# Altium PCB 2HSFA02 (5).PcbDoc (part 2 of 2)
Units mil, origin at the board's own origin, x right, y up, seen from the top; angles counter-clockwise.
Board outline 4391.67 x 3028.12 mil, 2 copper layers (Top Layer, Bottom Layer); 97 components, 133 nets, 219 pads, 38 vias.
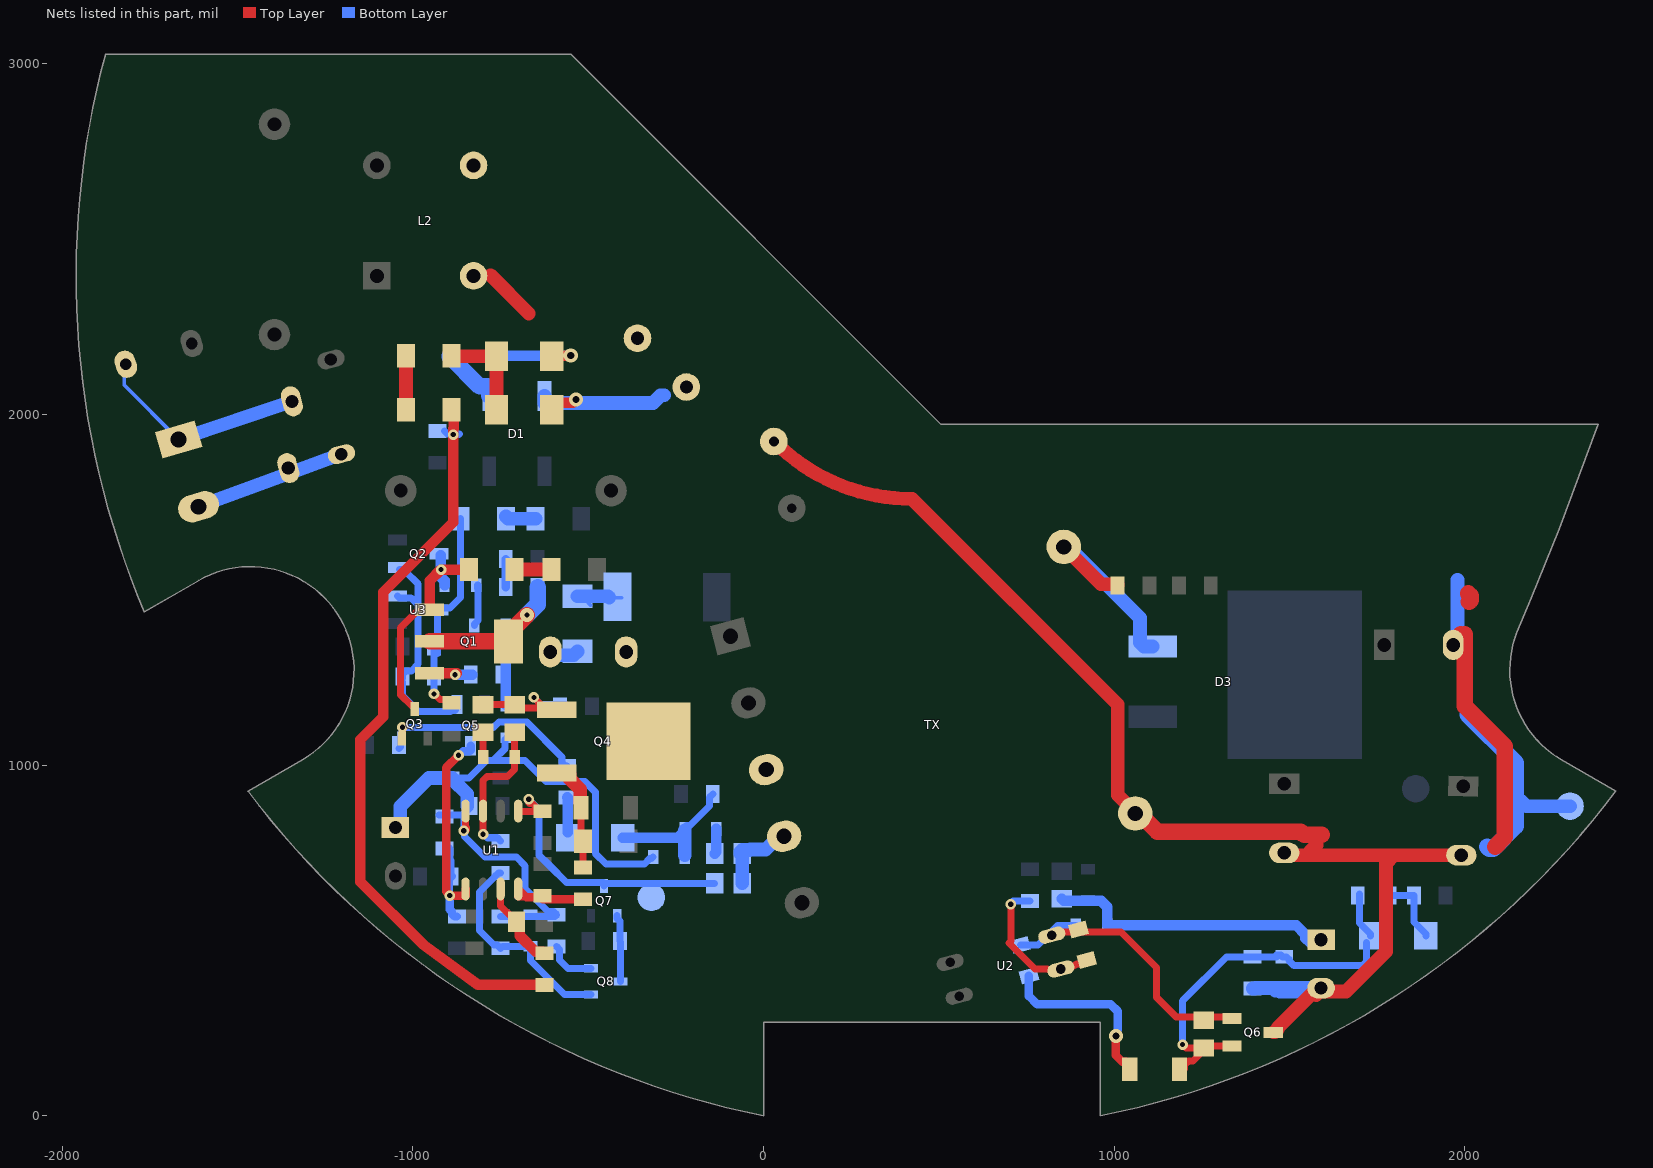
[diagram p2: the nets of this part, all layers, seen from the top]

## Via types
v1: diameter 30, hole 15, Top Layer to Bottom Layer, 22 vias
v2: diameter 40, hole 20, Top Layer to Bottom Layer, 15 vias
v3: diameter 39.37, hole 15, Top Layer to Bottom Layer, 1 vias

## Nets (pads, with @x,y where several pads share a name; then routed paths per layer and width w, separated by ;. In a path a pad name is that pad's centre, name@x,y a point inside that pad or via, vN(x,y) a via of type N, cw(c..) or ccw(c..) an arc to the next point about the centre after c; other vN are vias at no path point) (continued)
NetC8_1: C8.1 C13.2 D10.K D11.K D13.K D18.K R11.2 R30.1 R33.1 U1.8 | length 2063.7
  Top Layer w20: v1(-855,813) -848.83,813 -846.91,814.91 -846.91,821.98 -850.69,825.76 -850.69,868.53 U1.8@-850,869.22
  Top Layer w39.37: C8.1@-1050,821.9 -1040.16,821.9 C8.1@-1030.32,831.74
  Bottom Layer w20: R11.2@-926.16,858 -860.28,858 -849.98,868.29 -840.3,877.98 C13.2@-835.28,883 ; D13.K@-890.87,963 -887.91,963 -840,963 -790,1013 -771.77,1013 ; -854.96,855.73 -855,855.69 v1(-855,813) -853.09,811.09 -853.09,796.09 -795,738 -705,738 -680,713 -680,648 -614.96,582.96 -599.69,582.96 R33.1@-590,573.28 -595,568.28 -665,568.28 R30.1@-750,568.28 ; D10.K@-730,1078 -732.06,1078 -736.82,1073.24 -736.82,1047.95 -771.77,1013 ; D11.K@-315,738.08 -319.76,733.32 -324.69,733.32 -340,718 -450,718 -480,748 -480,923 -510,953 -620,953 -680,1013 -771.77,1013
  Bottom Layer w39.37: C8.1@-1050,821.9 -1046.06,821.9 -1036.21,831.74 -1036.21,881.79 -955,963 -893.82,963 D13.K@-890.87,963 ; D13.K@-887.91,963 -886.93,962.02 -886.93,959.06 -845.28,917.41 C13.2@-845.28,883
NetC9_2: C9.2 D9.K D11.A D12.K | length 406.6
  Bottom Layer w20: D12.K@-225,818 D12.K@-220,818 ; D12.K@-220.24,818 -220.24,827.69 -210.31,827.69 -154.41,883.59 -154.41,908.31 C9.2@-144.72,918
  Bottom Layer w30: D9.K@-401.26,793 -245,793 -225,813 D12.K@-225,818 D12.K@-225,813.55
  Bottom Layer w39.37: D11.A@-225,743 D12.K@-225,813.55
NetC10_2: C10.2 Q5.3 R11.1 R12.2 U1.1 | length 756.7
  Top Layer w24: v1(-870,1028) -905,993 -905,639.62 -895,629.62 v1(-895,628) -850.19,628 -850,628.19 U1.1@-850,646.78
  Bottom Layer w24: R11.1@-904.55,768.17 -896.41,760.04 -896.41,729.41 -893.96,726.96 -893.96,687.23 C10.2@-889.72,683 -897.41,675.31 -897.41,632.03 -895,629.62 v1(-895,628) -895,588.28 -888.59,581.87 -888.59,575.96 -880.91,568.28 R12.2@-875,568.28 ; v1(-870,1028) -868.38,1028 -857.05,1039.33 -839.38,1039.33 -835.63,1043.08 Q5.3@-835.63,1054.89
NetC11_1: C11.1 D14.A D17.K R20.1 | length 809
  Bottom Layer w30: R20.1@850,618.63 855.63,613 D14.A@925,613 962.43,613 980,595.43 D17.K@980,543 1518.9,543 1545.63,516.27 1545.63,506.43 1560.16,491.9 C11.1@1570,491.9
NetC12_1: C12.1 D17.A Q6.K R26.1 R27.2 U2.2 | length 832.4
  Top Layer w20: U2.2@843.17,517.18 849.91,523.92 U2.2@858.37,523.92 ; U2.2@858.39,523.94 R26.1@890.48,523.94 ; R26.1@898.28,531.74 R26.1@890.48,523.94 ; Q6.K@1320.94,282.37 1240,282.37 1176.26,282.37 1120.63,338 1120.63,422.37 1019.06,523.94 898.28,523.94 R26.1@890.48,523.94
  Bottom Layer w20: R27.2@733.28,486.73 782.27,486.73 U2.2@810.66,515.12 ; U2.2@821.95,515.12 U2.2@810.66,515.12 ; D17.A@890,543 838.54,543 U2.2@810.66,515.12
NetC12_2: C12.2 C15.2 D15.A Q6.REF R21.1 R32.2 R78.2 | length 1136.2
  Top Layer w20: v1(1195,203) 1204.37,193.63 C12.2@1255,193.63 ; C15.2@1200.87,133 1200.87,144.81 1212.52,156.47 1224.33,156.47 1258.25,190.38 1266.5,198.63 Q6.REF@1335.94,198.63
  Bottom Layer w20: v1(1195,203) 1195,328 1320.28,453.28 R78.2@1395,453.28 R32.2@1463.46,453.28 ; R32.2@1463.46,457.96 1475.31,457.96 R32.2@1480,453.28 ; R32.2@1485,453.28 1490.91,453.28 1500.59,443.59 1500.59,439.72 1512.31,428 1708.28,428 1720,439.72 D15.A@1720,494.26 ; R21.1@1700,632.21 1700,550.17 1731.26,518.91 D15.A@1731.26,513
NetC14_1: C14.1 D18.A Q8.1 R30.2 | length 614.1
  Bottom Layer w20: C14.1@-750,692.72 -755.91,692.72 -765.59,683.04 -765.59,682.41 -810,638 -810,528 -769.41,487.41 -759.69,487.41 R30.2@-750,477.72 -744.72,483 D18.A@-665,483 -665,443 -567.6,345.6 Q8.1@-492.32,345.6
NetC14_2: C14.2 D16.K R18.1 U1.7 | length 420.2
  Top Layer w20: v1(-800,803) -800,956.28 -788.28,968 -730,968 -710.94,987.06 -710.94,1022.06 D16.K@-710,1023 R18.1@-710,1093.63
  Bottom Layer w20: v1(-800,803) -797.29,803 -787.25,792.96 -759.69,792.96 C14.2@-750,783.28
NetC15_1: C15.1 R27.1 | length 512.4
  Top Layer w24: v2(1005,228) 1005,172.13 1022.67,154.46 1034.48,154.46 1044.13,144.81 C15.1@1044.13,133
  Bottom Layer w24: R27.1@756.72,399.27 756.72,341.28 780,318 990,318 1010,298 1010,244.31 1008.06,242.38 1008.06,235.39 v2@1009.26,234.19
NetC16_2: C16.2 Q7.3 R16.2 TP_TZE.TP U1.5 | length 839.5
  Top Layer w20: U1.5@-700,869.22 -699.05,868.28 -645.59,868.28 C16.2@-635.91,868.28 ; v1(-670,903) -670,893 -668.09,891.09 -658.72,891.09 C16.2@-635.91,868.28 ; C16.2@-630,868.28 C16.2@-635.91,868.28
  Bottom Layer w20: v1(-670,903) -640,873 -640,743 -610,713 -562.01,665.01 -456.81,665.01 -455,663.2 Q7.3@-455,661.19 ; Q7.3@-455,655.32 Q7.3@-455,661.19 ; R16.2@-139.37,663 -453.19,663 Q7.3@-455,661.19
NetC17_1: C17.1 R25.1 U1.4 | length 233.1
  Top Layer w24: -684.33,626.3 -699.81,626.3 -700,626.49 U1.4@-700,646.78 -676.22,623 -635.28,623 -630,617.72 R25.1@-515,617.72
NetC19_2: C19.2 R82.2 U1.3 | length 253.2
  Top Layer w20: U1.3@-750,646.78 -750,598 -719.53,567.53 -718.98,567.53 -714.37,562.92 C19.2@-714.37,543
  Top Layer w30: C19.2@-704.37,553 -694.76,543.39 -694.76,512.76 -650.24,468.24 -629.69,468.24 R82.2@-625,463.55
NetC20_2: C20.2 R23.2 R24.1 R31.2 U3.3 | length 627.3
  Top Layer w20: v1(-940,1203) -938.6,1203 -923.28,1187.69 -899.69,1187.69 R31.2@-890,1178
  Bottom Layer w20: v1(-940,1203) -939.72,1203.28 R24.1@-939.72,1253 -939.72,1318 C20.2@-939.72,1338 -930,1347.72 -930,1437.25 U3.3@-924.25,1443 ; C20.2@-929.72,1318 C20.2@-929.72,1338 ; U3.3@-925.95,1443 U3.3@-924.25,1443 ; R23.2@-864.96,1703 -864.96,1478.04 -894.25,1448.75 -918.5,1448.75 U3.3@-924.25,1443
NetC23_1: 
NetC23_2: 
NetC25_1: 
NetC32_1: 
NetC37_1: 
NetC39_2: 
NetD1_2: D1.2 D7.A L1.2 | length 452.9
  Top Layer w30: D7.A@-604.26,2014 -604.26,2015.12 -585.8,2033.58 -544.42,2033.58 v2(-535,2043)
  Bottom Layer w39.37: D1.2@-625,2053 -625,2033 -535,2033 -315.56,2033 -293.7,2054.86 -283.05,2054.86
NetD1_4: D1.4 D6.A L2.3 | length 575
  Top Layer w30: D6.A@-604.26,2166 -603.26,2167 -551,2167 v2(-550,2168)
  Bottom Layer w30: -895,2168 v2(-550,2168)
  Bottom Layer w47.24: -895,2168 -895,2165.52 -809.8,2080.32 -787.16,2080.32 -782.48,2075.64 D1.4@-782.48,2053
NetD2_K: D2.K D4.K | length 247.2
  Bottom Layer w10: D4.K@-529.3,1482.44 -530,1481.74 -526.26,1478 -511.97,1478 -440,1478 D2.K@-405,1478 ; D4.K@-511.97,1474.82 D4.K@-492.68,1455.53
  Bottom Layer w39.37: D4.K@-530.83,1481.74 -530,1481.74 -443.74,1481.74 D2.K@-440,1478
NetD3_A: D3.A R1.1 TX.10 | length 612.9
  Top Layer w39.37: TX.10@856.38,1622.52 962.78,1516.11 1009.72,1516.11 R1.1@1009.72,1513
  Bottom Layer w39.37: TX.10@856.38,1622.52 870.48,1622.52 1073.4,1419.6 1073.4,1349.81 1085.22,1338 D3.A@1110,1338
NetD4_A: D4.A R6.2 | length 91.2
  Bottom Layer w39.37: R6.2@-613.27,1303 -602.64,1313.63 -541.45,1313.63 D4.A@-530.83,1324.26
NetD5_A: D5.A Q1.1 Q2.3 Q3.3 R4.1 | length 654.6
  Top Layer w20: Q3.3@-995,1160.32 -995,1168.2 -996.81,1170.01 -1004.68,1170.01 -1035,1200.32 -1035,1393 -992.17,1435.83 -959.92,1435.83 Q1.1@-952.2,1443.55
  Top Layer w30: Q1.1@-952.2,1443.55 -952.2,1525.8 v1(-920,1558) R4.1@-839.96,1558
  Bottom Layer w30: v1@-920.95,1558 Q2.3@-920.95,1598 ; v1(-920,1558) -920,1535.5 -910,1525.5 D5.A@-910,1513
NetD5_K: D5.K D8.A | length 120.3
  Bottom Layer w20: D8.A@-825,1398 -825,1402.92 -815,1412.92 -815,1503.08 -815.24,1503.31 D5.K@-815.24,1514.07
NetD6_K: D6.K D7.K R13.1 | length 281.1
  Top Layer w39.37: R13.1@-890.04,2168 -888.04,2166 D6.K@-761.74,2166 D7.K@-761.74,2014
NetD8_K: D8.K D10.A R7.1 | length 225
  Bottom Layer w30: D10.A@-735,1173 -735,1258 D8.K@-735,1398
NetD9_A: D9.A R8.1 | length 100.2
  Bottom Layer w30: R8.1@-560,907.72 -558.74,906.46 D9.A@-558.74,808
NetD12_A: D12.A R10.1 | length 71.8
  Bottom Layer w30: R10.1@-139.37,748 -135,752.37 D12.A@-135,818
NetD15_K: D15.K R15.1 R21.2 | length 198.5
  Bottom Layer w20: R21.2@1785.27,628 R15.1@1854.72,628 1854.72,552.92 1888.74,518.91 D15.K@1888.74,513
NetD16_A: D16.A R22.1 | length 70.6
  Top Layer w20: D16.A@-800,1023 R22.1@-800,1093.63
NetD19_K: 
NetF1_1: F1.1 RV1.1 X1.1 | length 629.9
  Bottom Layer w10: F1.1@-1823.87,2153.42 -1823.87,2084.14 X1.1@-1668.57,1928.83
  Bottom Layer w39.37: X1.1@-1668.57,1928.83 RV1.1@-1345.41,2037.66
NetIRX1_1: 
NetL1_1: L1.1 L2.4 | length 154.9
  Top Layer w39.37: -779.2,2397.52 -669.69,2288
NetLED3_K: 
NetLED4_K: 
NetLED5_K: 
NetLED6_K: 
NetLED7_K: 
NetLED8_K: 
NetLED9_B: 
NetLED9_G: 
NetLED9_R: 
NetP1_2: 
NetP1_3: 
NetP3_1: 
NetP3_2: 
NetQ1_2: Q1.2 Q1.4 R5.1 | length 413.8
  Top Layer w47.24: Q1.2@-952.2,1353 Q1.4@-727.8,1353 -710.08,1370.72 -710.08,1392.92 v3(-675,1428)
  Bottom Layer w47.24: v3(-675,1428) -644.72,1458.28 R5.1@-644.72,1508
NetQ1_3: Q1.3 R7.2 | length 134.9
  Top Layer w30: Q1.3@-952.2,1262.45 -874.45,1262.45 -878.9,1258 v1(-880,1258)
  Bottom Layer w30: v1(-880,1258) R7.2@-830.28,1258
NetQ2_1: Q2.1 Q5.1 R24.2 U3.2 | length 654.4
  Bottom Layer w20: U3.2@-1044.06,1482.37 -1038.31,1476.62 -1005,1476.62 -985,1456.62 ; Q2.1@-1039.06,1558.63 -1027.24,1558.63 -1021.5,1552.88 -985,1516.39 -985,1456.62 ; R24.2@-1030.27,1237.41 -1030.27,1198.27 -985,1153 -892.46,1153 -890.02,1155.44 -880.75,1155.44 -879.37,1156.82 Q5.1@-879.37,1162.05 ; R24.2@-1030.27,1247.09 R24.2@-1030.27,1253 -1030.27,1258.9 -1020.59,1268.59 -1004.41,1268.59 -985,1288 -985,1456.62
NetQ3_1: Q3.1 R8.2 R9.2 | length 634.7
  Top Layer w20: Q3.1@-1032.4,1075.68 -1030.59,1077.49 -1030.59,1094.84 -1030,1095.43 v1(-1030,1108)
  Bottom Layer w20: R9.2@-1039.72,1048 -1036.13,1051.6 -1036.13,1091.87 -1031.91,1096.09 -1031.91,1103.38 -1030.56,1104.73 v1@-1026.73,1104.73 ; v1(-1030,1108) -770,1108 -755,1123 -675,1123 -575.59,1023.59 -575.59,1007.96 -565.91,998.28 R8.2@-560,998.28
NetQ4_1: Q4.1 R18.2 R22.2 R77.2 | length 330.5
  Top Layer w20: R22.2@-800,1172.37 R18.2@-710,1172.37 -700.63,1163 Q4.1@-627.09,1163 ; v1(-655,1193) -635.71,1173.71 -635.71,1171.62 Q4.1@-627.09,1163 ; Q4.1@-613.15,1163 Q4.1@-627.09,1163
  Bottom Layer w20: v1(-655,1193) -635.28,1173.28 R77.2@-565,1173.28
NetQ4_2: Q4.2 R6.1 TX.3 | length 230.2
  Top Layer w39.37: Q4.2@-362.09,999.28 cw(c-325.56,1020.37) -366.3,1031.29 -361.81,1048.04 -357.2,1065.26 Q4.2@-356.11,1069.33 ; Q4.2@-340.44,1060.77 cw(c-414.36,1018.09) -331.91,996 -332.58,993.5 -333.5,995.09 Q4.2@-353.54,1029.8 ; Q4.2@-353.54,1029.8 -349.54,1044.75 -350.92,1047.14 -354.92,1032.19 Q4.2@-353.54,1029.8
  Bottom Layer w20: TX.3@-2.09,987.49 TX.3@7.56,987.49
NetQ4_3: Q4.3 R25.2 R28.2 R76.2 | length 295.1
  Top Layer w20: R25.2@-520.91,708.28 R25.2@-515,708.28 R25.2@-515,708.28 R76.2@-514.96,783 ; R76.2@-520.87,798 R28.2@-520.87,878
  Top Layer w39.37: Q4.3@-590,977.68 -557.91,977.68 -553.98,973.75 -553.98,961.98 -522.83,930.83 -522.83,891.78 R28.2@-520.87,891.78
NetQ7_1: Q7.1 Q8.3 R34.2 | length 191.8
  Bottom Layer w20: Q7.1@-417.6,570.68 -417.6,562.8 -409.72,554.93 R34.2@-409.72,498 -407.68,495.95 Q8.3@-407.68,383
NetQ8_2: Q8.2 R33.2 | length 140.9
  Bottom Layer w20: R33.2@-590,482.72 -581.76,474.48 -581.76,444.76 -557.4,420.4 Q8.2@-492.32,420.4
NetQ9_1: 
NetQ10_3: 
NetQ11_3: 
NetQ12_1: 
NetR2_1: R2.1 R5.2 | length 80
  Bottom Layer w24: R5.2@-735.28,1508 R2.1@-735.28,1588
NetR3_1: R3.1 R4.2 | length 105.1
  Top Layer w39.37: R4.2@-710.04,1558 R3.1@-604.96,1558
NetR10_2: R10.2 R16.1 TX.4 | length 239.5
  Bottom Layer w39.37: R10.2@-65.63,748 R10.2@-65.63,752.92 ; R16.1@-60.63,663 -60.63,747.92 R10.2@-65.63,752.92 ; TX.4@58.51,797.35 43.93,797.35 6.12,759.53 -37.65,759.53 -39.33,757.84 -60.71,757.84 R10.2@-65.63,752.92
NetR13_2: R13.2 R14.1 | length 155
  Top Layer w39.37: R14.1@-1019.96,2013 R13.2@-1019.96,2168
NetR14_2: R14.2 R29.2 R82.1 | length 2161.1
  Top Layer w20: R14.2@-890.04,2013 R14.2@-883.25,2006.21
  Top Layer w30: R14.2@-883.25,2006.21 -883.25,1961.25 -885,1959.5 -885,1693 -1085,1493 -1085,1138 -1150,1073 -1150,668 -968.45,486.45 -966.82,484.82 -814,373 R82.1@-625,373
  Bottom Layer w20: R29.2@-910,1953.28 -901.64,1944.91 -866.91,1944.91 -868.83,1943 v1(-885,1943)
NetR17_1: R17.1 R23.1 | length 87.5
  Bottom Layer w39.37: R23.1@-735.04,1708.91 -729.13,1703 R17.1@-649.96,1703
NetR19_1: R19.1 R26.2 U2.1 | length 440.1
  Top Layer w20: v1(705,603) 705,498 700,493 774.47,418.53 810.02,418.53 811.41,417.14 846.44,417.14 U2.1@847.83,418.53 856.63,427.33 884.25,427.33 887.47,430.55 890.18,430.55 892.6,432.96 910.41,432.96 R26.2@921.71,444.27
  Bottom Layer w20: v1(705,603) 702.71,603 711.76,612.05 759.33,612.05 R19.1@760,612.72
NetR35_1: 
NetR37_1: 
NetR38_1: 
NetR39_1: 
NetR40_1: 
NetR43_1: 
NetR44_2: 
NetR47_1: 
NetR54_2: 
NetR55_2: 
NetR61_1: 
NetR62_2: 
NetR63_1: 
NetR64_1: 
NetR66_2: 
NetR67_1: 
NetR69_1: 
NetR70_1: 
NetR71_2: 
NetR72_2: 
NetR73_2: 
NetR74_1: 
NetRT1_1: RT1.1 RV1.2 X1.2 | length 434.1
  Bottom Layer w39.37: X1.2@-1611.43,1737.17 -1350.34,1833.19 RT1.1@-1204,1887
NetTP8_TP: 
NetU4_21: 
NetU4_28: 
NetU4_34: 
NetU4_35: 
NetU7_17: 
NetU7_19: 
PGND: C1.2 C5.2 C6.2 C7.2 C11.2 Q6.A R32.1 R78.1 TP_GND.TP TX.6 | length 5413.9
  Top Layer w39.37: C1.2@32.63,1921.37 ccw(c423.55,2312.29) 423.55,1759.45 1010,1173 1010,914.92 1060.07,864.85 TX.6@1060.07,862.33 ; Q6.A@1454.05,238 1457.99,238 1465.87,245.87 1465.87,249.81 C11.2@1570.16,354.1 ; C7.2@1485.09,749.92 1488.86,746.15 1516.56,746.15 1519.71,743 1798.06,743 ; 1560,755.44 1577.15,772.59 1577.15,789.63 1588.51,800.99 ; C11.2@1570,354.1 C11.2@1570.16,354.1 ; C11.2@1576.39,344.39 C11.2@1576.39,354.1 ; C11.2@1576.39,365.01 C11.2@1576.39,360.34 ; C6.2@1990,743 1798.06,743 ; C11.2@1570.16,354.1 C11.2@1576.39,354.1 ; C11.2@1570.16,354.1 C11.2@1576.39,360.34 ; C11.2@1576.39,354.1 C11.2@1576.39,360.34 ; C11.2@1576.39,354.1 1661.1,354.1 1775,468 1775,719.94 1798.06,743
  Top Layer w47.24: TX.6@1060.07,862.33 1070.72,862.33 1123.05,810 1532.45,810 1541.46,800.99 1588.51,800.99 1590.9,800.99 1591.95,802.04 ; C5.2@1988.43,1343 C5.2@1988.43,1372.91 ; 2000,1373.09 2000,1168.28 2113.86,1054.42 2113.86,794.59 2086.3,767.03 ; 2010,1489.52 2016.83,1482.68 2016.83,1470.45 2011.87,1465.49
  Bottom Layer w39.37: R78.1@1395,362.72 1400.91,362.72 1402.28,364.1 C11.2@1590,364.1 ; R32.1@1460.28,363 1460.28,357.09 1469.33,357.09 1472.32,354.1 C11.2@1570,354.1 ; R32.1@1465,357.72 1485,357.72 1545,357.72 ; C5.2@1966.85,1343 1966.85,1362.11 1978.74,1374 1978.74,1528 ; 2145.35,898 2160,898 2175,883 TP_GND.TP@2300,883
  Bottom Layer w47.24: TX.6@1060.07,862.33 TX.6@1070.72,862.33 ; 2008,1144.53 2145.35,1007.17 2145.35,898 2145.35,826.07 2080.54,761.25 2069.64,761.25 2063.88,767.02
R_LED: 
RESET: 
SW_BK: 
pads on no net: D3.NC TX.2

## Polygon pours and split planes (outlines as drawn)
+24V on Top Layer "+24V_L01_P137" (solid, pour order 137): 1435,1713 1435,1378 1405,1348 1300,1348 1250,1398 1250,1638 1335,1723 1425,1723
+24V on Top Layer "+24V_L01_P086" (solid, pour order 86): 1640,1458 1775,1593 1885,1593 1900,1578 1900,1513 1830,1443 1830,1273 1795,1238 1675,1238 1640,1273
PGND on Top Layer "PGND_L01_P035" (solid, pour order 35): 2010,703 2020,693 2180,693 2200,713 2200,1043 2100,1143 2075,1168 2075,1498 2060,1513 1980,1513 1895,1428 1895,1188 2070,1013 2070,833 2054.25,817.25 2014.25,817.25 2010,813
PGND on Top Layer "PGND_L01_P031" (solid, pour order 31): 990,913 990,728 1015,703 1570,703 1660,703 1670,713 1670,833 1650,853 1280,853 1190,943 1020,943
HVGND on Top Layer "HVGND_L01_P087" (solid, pour order 87): -795,1883 -795,1718 -770,1693 -635,1693 -590,1738 -590,1798 -515,1873 -365,1873 190,1318 190,758 130,698 25,698 -25,648 -25,543 15,503 300,503 355,558 355,1303 -290,1948 -540,1948 -585,1903 -775,1903
HVGND on Top Layer "HVGND_L01_P088" (solid, pour order 88): -295,1848 -320,1823 -320,1548 -310,1538 -15,1538 -10,1543 -295,1828
HVGND on Top Layer "HVGND_L01_P098" (solid, pour order 98): -445,473 -435,463 325,463 355,493 355,593 250,698 -30,698 -85,753 -85,873 -125,913 -435,913 -445,903
HVGND on Top Layer "HVGND_L01_P099" (solid, pour order 99): -1100,678 -1060,638 -950,638 -940,648 -940,1013 -875,1078 -875,1103 -880,1108 -965,1108 -980,1093 -980,1053 -1085,948 -1085,893 -1080,888 -995,888 -985,878 -985,758 -990,753 -1095,753 -1100,748
NetQ4_2 on Top Layer "NETQ4_2_L01_P100" (solid, pour order 100): -70,953 -50,933 50,933 75,958 75,1053 55,1073 -70,1073 -190,1193 -440,1193 -450,1183 -450,958 -445,953
NetQ4_2 on Top Layer "NETQ4_2_L01_P101" (solid, pour order 101): -400,1088 -450,1138 -450,1403 -430,1423 -275,1423 -255,1403 -255,1258 -178.32,1181.32 -178.32,1086.32
HVGND on Top Layer "HVGND_L01_P097" (solid, pour order 97): -735,818 -720,803 -605,803 -580,778 -580,703 -595,688 -655,688 -680,713 -850,713 -855,718 -855,753 -850,758 -770,758 -760,768 -760,918 -755,923 -740,923 -735,918
HVGND on Top Layer "HVGND_L01_P104" (solid, pour order 104): -425,613 -455,583 -645,583 -650,578 -650,523 -645,518 -580,518 -525,463 -425,463 -390,498 -390,613
HVGND on Top Layer "HVGND_L01_P107" (solid, pour order 107): -795,493 -805,503 -855,503 -940,588 -940,693 -975,728 -1065,728 -1085,708 -1085,663 -880,458 -800,458 -795,463
HVGND on Top Layer "HVGND_L01_P109" (solid, pour order 109): -985,1023 -1060,1023 -1085,998 -1085,938 -1075,928 -985,928
NetQ4_3 on Top Layer "NETQ4_3_L01_P111" (solid, pour order 111): -655,1008 -655,958 -645,948 -585,948 -550,913 -550,753 -540,743 -490,743 -485,748 -485,913 -500,928 -500,998 -515,1013 -650,1013
NetL1_1 on Top Layer "NETL1_1_L01_P112" (solid, pour order 112): -870,2418 -870,2368 -755,2253 -465,2253 -385,2173 -335,2173 -315,2193 -315,2293 -325,2303 -585,2303 -725,2443 -845,2443
PGND on Top Layer "PGND_L01_P125" (solid, pour order 125): 1545,793 1605,853 1705,853 1740.75,817.25 2030.75,817.25 2045,803 2045,718 2020,693 1025,693 990,728 990,913 995,918 1100,918 1225,793
+24V on Bottom Layer "+24V_L02_P126" (solid, pour order 126): 1385,993 1395,993 1430,1028 1985,1028 2040,973 2040,883 2020,863 1785,863 1740,908 1405,908 1385,928
NetD3_A on Bottom Layer "NETD3_A_L02_P122" (solid, pour order 122): 775,1383 880,1278 1190,1278 1200,1288 1200,1428 935,1693 790,1693 775,1678
+24V on Bottom Layer "+24V_L02_P032" (solid, pour order 32): 1745,1393 1745,928 1810,863 2020,863 2040,883 2040,973 1880,1133 1880,1393 1870,1403 1755,1403
PGND on Bottom Layer "PGND_L02_P059" (solid, pour order 59): 2010,778 2080,848 2080,998 1935,1143 1935,1398 1945,1408 2035,1408 2050,1393 2050,1203 2235,1018 2235,758 2180,703 2035,703 2010,728
HVGND on Bottom Layer "HVGND_L02_P089" (solid, pour order 89): -310,1688 -235,1688 -225,1678 -225,888 -255,858 -440,858 -445,863 -445,973 -520,1048 -520,1198 -510,1208 -325,1208 -315,1218 -315,1683
HVGND on Bottom Layer "HVGND_L02_P090" (solid, pour order 90): -740,1788 -720,1808 -720,1888 -725,1893 -1010,1893 -1095,1808 -1095,1628 -1085,1618 -1010,1618 -990,1638 -990,1753 -955,1788
HVGND on Bottom Layer "HVGND_L02_P091" (solid, pour order 91): -990,1713 -1100,1603 -1100,923 -1135,888 -1135,748 -1125,738 -975,738 -955,718 -955,423 -1250,678 -1300,733 -1300,998 -1184.29,1113.71 ccw(c-1255,1184.42) -1155,1184.42 -1155,1748 -1085,1818 -990,1818
HVGND on Bottom Layer "HVGND_L02_P092" (solid, pour order 92): -1110,1453 -1085,1428 -1020,1428 -1015,1423 -1015,1313 -1020,1308 -1090,1308 -1105,1293 -1110,1298
NetC1_1 on Bottom Layer "NETC1_1_L02_P093" (solid, pour order 93): -650,1888 -650,1798 -640,1788 -580,1788 -565,1773 -565,1673 -615,1623 -660,1623 -665,1618 -665,1563 -660,1558 -590,1558 -500,1648 -500,1858 -535,1893 -645,1893
NetC1_1 on Bottom Layer "NETC1_1_L02_P094" (solid, pour order 94): -575,1863 -545,1893 -135,1893 -35,1793 -35,1328 -65,1298 -145,1298 -175,1328 -175,1708 -205,1738 -490,1738 -505,1723 -545,1723 -545,1828 -555,1838
NetD4_A on Bottom Layer "NETD4_A_L02_P095" (solid, pour order 95): -645,1368 -640,1373 -490,1373 -485,1368 -485,1288 -495,1278 -640,1278 -645,1283
NetD2_K on Bottom Layer "NETD2_K_L02_P096" (solid, pour order 96): -575,1513 -575,1448 -570,1443 -500,1443 -465,1408 -380,1408 -375,1413 -375,1548 -380,1553 -455,1553 -490,1518 -570,1518
HVGND on Bottom Layer "HVGND_L02_P102" (solid, pour order 102): -780,978 -780,833 -775,828 -710,828 -705,823 -705,768 -700,763 -675,763 -665,773 -665,858 -670,863 -690,863 -720,893 -720,978 -725,983 -775,983
NetC8_1 on Bottom Layer "NETC8_1_L02_P103" (solid, pour order 103): -1095,853 -1095,793 -1090,788 -1010,788 -1005,793 -1005,873 -965,913 -880,913 -870,903 -870,867.72 -860.28,858 -820,858 -815,863 -815,938 -855,978 -970,978
HVGND on Bottom Layer "HVGND_L02_P105" (solid, pour order 105): -480,603 -475,598 -475,473 -480,468 -530,468 -535,473 -535,598 -530,603
HVGND on Bottom Layer "HVGND_L02_P108" (solid, pour order 108): -970,573 -905,508 -850,508 -825,483 -825,348 -830,343 -959.55,426.93 -970,437.38
HVGND on Bottom Layer "HVGND_L02_P106" (solid, pour order 106): -1130.28,1048 -1080.28,998 -1010,998 -990,1018 -990,1073 -980,1083 -910,1083 -905,1078 -905,1023 -930,998 -970,998 -1055,913 -1120,913 -1130,923
HVGND on Bottom Layer "HVGND_L02_P082" (solid, pour order 82): 75,663 260,663 280,643 280,303 270,293 -25,293 -35,283 -35,63 -60,38 -100,38 -185,58 -350,113 -500,168 -585,213 -585,228 -575,238 -315,238 -275,278 -275,458 -175,558 -39.55,558
HVGND on Bottom Layer "HVGND_L02_P110" (solid, pour order 110): -915,503 -845,503 -815,473 -815,448 -805,438 -730,438 -590,298 -370,298 -335,333 -335,513 -290,558 -150,558 -35,443 -35,153 -95,93 -160,158 -445,158 -477.5,190.5 -542.5,190.5 -645,238 -740,288 -830,343 -915,428
NetD1_2 on Bottom Layer "NETD1_2_L02_P113" (solid, pour order 113): -315,2098 -650,2098 -655,2093 -655,2013 -650,2008 -215,2008 -180,2043 -180,2123 -190,2133 -280,2133
NetD1_4 on Bottom Layer "NETD1_4_L02_P114" (solid, pour order 114): -760,2008 -770,1998 -840,1998 -980,2138 -980,2623 -835,2768 -785,2768 -765,2748 -765,2683 -910,2538 -910,2238 -760,2088
NetC2_1 on Bottom Layer "NETC2_1_L02_P115" (solid, pour order 115): -1685,2293 -1605,2373 -1605,2708 -1435,2878 -1130,2878 -1055,2803 -1055,2673 -1070,2658 -1420,2658 -1495,2583 -1495,2278 -1610,2163 -1675,2163 -1685,2173
NetC2_2 on Bottom Layer "NETC2_2_L02_P116" (solid, pour order 116): -1065,2453 -1055,2443 -1055,2343 -1070,2328 -1145,2328 -1190,2283 -1190,2133 -1200,2123 -1265,2123 -1315,2173 -1435,2173 -1445,2183 -1445,2258 -1250,2453
NetF1_1 on Bottom Layer "NETF1_1_L02_P118" (solid, pour order 118): -1890,2193 -1870,2213 -1810,2213 -1685,2088 -1325,2088 -1310,2073 -1310,2003 -1330,1983 -1345,1983 -1730,1863 -1820,1863 -1890,1933
NetRT1_1 on Bottom Layer "NETRT1_1_L02_P119" (solid, pour order 119): -1215,1953 -1740,1763 -1750,1753 -1740,1698 -1695,1653 -1160,1868 -1155,1873 -1155,1898 ccw(c-1239.49,1898) -1179.75,1957.75 -1185,1963
NetL1_1 on Bottom Layer "NETL1_1_L02_P120" (solid, pour order 120): -850,2443 -870,2423 -870,2368 -755,2253 -475,2253 -390,2168 -335,2168 -315,2188 -315,2268 -350,2303 -585,2303 -725,2443
NetR10_2 on Bottom Layer "NETR10_2_L02_P121" (solid, pour order 121): -50.02,757.84 -50.02,782.98 20,853 100,853 115,838 115,778 120,773 90,743 -20,743 -35,728 -40,728
PGND on Bottom Layer "PGND_L02_P124" (solid, pour order 124): 1000,798 1025,773 1150,773 1225,698 1510,698 1540,728 1540,793 1515,818 1320,818 1185,953 1010,953 1000,943
PGND on Bottom Layer "PGND_L02_P127" (solid, pour order 127): 2030,1358 2050,1378 2050,1548 2025,1573 1945,1573 1935,1563 1935,1388 1965,1358
HVGND on Bottom Layer "HVGND_L02_P147" (solid, pour order 147): 50,558 205,403 565,403 585,423 585,488 565,508 325,508 175,658 85,658 45,618 45,583

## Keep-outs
Keep-Out Layer:
  lines w10: -1765.9,1437.31 -1765.9,1437.31 ; -1315.67,1015.34 -1315.67,1015.34 ; 2275.94,1015.34 2275.94,1015.34

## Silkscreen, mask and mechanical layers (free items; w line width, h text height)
Top Overlay:
  lines w0.5: -362.07,429.14 -362.07,460.64 -331.74,460.64 cw(c-189.3,444.89) -205.05,587.33 -205.05,617.66 -173.55,617.66 -173.55,587.33 cw(c-189.3,444.89) -46.86,460.64 -16.52,460.64 -16.52,429.14 -46.86,429.14 cw(c-189.3,444.89) -173.55,302.45 -173.55,272.11 -205.05,272.11 -205.05,302.45 cw(c-189.3,444.89) -331.74,429.14 -362.07,429.14 ; -361.82,1767.56 -361.82,1799.05 -331.48,1799.05 cw(c-189.04,1783.31) -204.79,1925.75 -204.79,1956.08 -173.3,1956.08 -173.3,1925.75 cw(c-189.04,1783.31) -46.6,1799.05 -16.27,1799.05 -16.27,1767.56 -46.6,1767.56 cw(c-189.04,1783.31) -173.3,1640.87 -173.3,1610.53 -204.79,1610.53 -204.79,1640.87 cw(c-189.04,1783.31) -331.48,1767.56 -361.82,1767.56 ; 976.26,429.23 976.26,460.72 1006.6,460.72 cw(c1149.04,444.98) 1133.29,587.42 1133.29,617.75 1164.79,617.75 1164.79,587.42 cw(c1149.04,444.98) 1291.48,460.72 1321.81,460.72 1321.81,429.23 1291.48,429.23 cw(c1149.04,444.98) 1164.79,302.54 1164.79,272.2 1133.29,272.2 1133.29,302.54 cw(c1149.04,444.98) 1006.6,429.23 976.26,429.23
  lines w5: -1034.28,1203.72 -922,1203.72 ; -755,1213 -765,1203 ; -675,1063 -660,1063 -655,1068 ; -650,928 -615,928 -598,911 -598,894 ; -598,602 -579,602 -557.5,580.5 ; -595,518 -580,503 -575,503 ; -765,1203 -765,1203
  lines w6: -1901.18,2015.86 -1770.74,1529.02 -1360.36,1653.69 -1496.62,2133.94 -1901.18,2015.86
Bottom Overlay:
  lines w0.5: 976.51,1799.12 976.51,1767.62 1006.85,1767.62 ; -362.05,1767.58 -362.05,1799.08 -331.71,1799.08 cw(c-189.27,1783.33) -205.02,1925.77 -205.02,1956.11 -173.53,1956.11 -173.53,1925.77 cw(c-189.27,1783.33) -46.83,1799.08 -16.5,1799.08 -16.5,1767.58 -46.83,1767.58 cw(c-189.27,1783.33) -173.53,1640.89 -173.53,1610.56 -205.02,1610.56 -205.02,1640.89 cw(c-189.27,1783.33) -331.71,1767.58 -362.05,1767.58 ; -361.94,429.14 -361.94,460.64 -331.61,460.64 cw(c-189.17,444.89) -204.92,587.33 -204.92,617.66 -173.42,617.66 -173.42,587.33 cw(c-189.17,444.89) -46.73,460.64 -16.39,460.64 -16.39,429.14 -46.73,429.14 cw(c-189.17,444.89) -173.42,302.45 -173.42,272.12 -204.92,272.12 -204.92,302.45 cw(c-189.17,444.89) -331.61,429.14 -361.94,429.14 ; 976.39,429.23 976.39,460.73 1006.73,460.73 cw(c1149.17,444.98) 1133.42,587.42 1133.42,617.75 1164.92,617.75 1164.92,587.42 cw(c1149.17,444.98) 1291.61,460.73 1321.94,460.73 1321.94,429.23 1291.61,429.23 cw(c1149.17,444.98) 1164.92,302.54 1164.92,272.2 1133.42,272.2 1133.42,302.54 cw(c1149.17,444.98) 1006.73,429.23 976.39,429.23
  lines w5: -622,599 -622,606 -615,613 ; -530,448 -526,452 -526,466
Mechanical 2:
  circle w0.5: c-189.15,444.81 r59.45
  circle w0.5: c-189.15,1783.39 r59.45
  circle w0.5: c1149.43,444.81 r59.45
  lines w0.5: 976.65,1767.65 1006.99,1767.65 ; -361.93,429.06 -331.6,429.06 ccw(c-189.15,444.81) -204.9,302.37 -204.9,272.04 -173.41,272.04 -173.41,302.37 ccw(c-189.15,444.81) -46.71,429.06 -16.38,429.06 -16.38,460.56 -46.71,460.56 ccw(c-189.15,444.81) -173.41,587.25 -173.41,617.59 -204.9,617.59 -204.9,587.25 ccw(c-189.15,444.81) -331.6,460.56 -361.93,460.56 -361.93,429.06 ; -361.93,1767.65 -361.93,1799.14 -331.6,1799.14 cw(c-189.15,1783.39) -204.9,1925.83 -204.9,1956.17 -173.41,1956.17 -173.41,1925.83 cw(c-189.15,1783.39) -46.71,1799.14 -16.38,1799.14 -16.38,1767.65 -46.71,1767.65 cw(c-189.15,1783.39) -173.41,1640.95 -173.41,1610.62 -204.9,1610.62 -204.9,1640.95 cw(c-189.15,1783.39) -331.6,1767.65 -361.93,1767.65 ; 976.65,429.06 1006.99,429.06 ccw(c1149.43,444.81) 1133.68,302.37 1133.68,272.04 1165.18,272.04 1165.18,302.37 ccw(c1149.43,444.81) 1291.87,429.06 1322.2,429.06 1322.2,460.56 1291.87,460.56 ccw(c1149.43,444.81) 1165.18,587.25 1165.18,617.59 1133.68,617.59 1133.68,587.25 ccw(c1149.43,444.81) 1006.99,460.56 976.65,460.56 976.65,429.06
